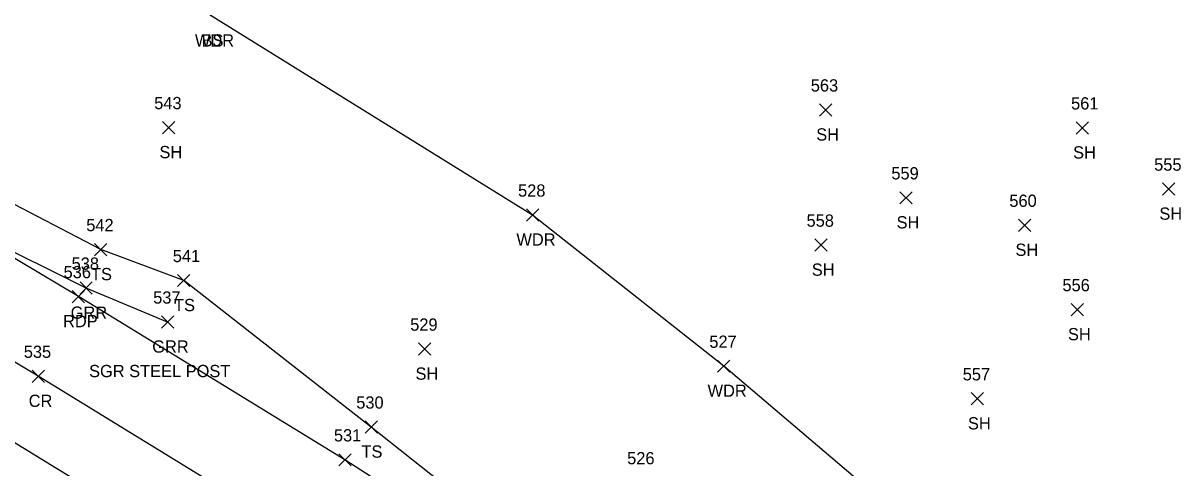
# Model space of a CAD drawing. Extents: x 1629176 to 1637209, y 606063 to 610167.
# Drawn here: x 1630613 to 1630801.8, y 606647 to 606719.6 of the extents above; entities that cross this region are included whole.
import ezdxf

# ---------------------------------------------------------------- set-up
doc = ezdxf.new("R2010")
doc.units = 0
for name, color, linetype in [('L_A', 7, 'Continuous'), ('L_I', 7, 'Continuous'), ('L_TIC', 7, 'Continuous'), ('LAWA', 7, 'Continuous'), ('LELB', 7, 'Continuous'), ('P_A', 7, 'Continuous'), ('P_I', 7, 'Continuous'), ('P_TIC', 7, 'Continuous'), ('PET', 7, 'Continuous'), ('PRC', 7, 'Continuous'), ('R_A', 7, 'Continuous'), ('R_C', 7, 'Continuous'), ('R_I', 7, 'Continuous'), ('R_TIC', 7, 'Continuous'), ('RGR', 7, 'Continuous')]:
    doc.layers.add(name, color=color, linetype=linetype)

msp = doc.modelspace()

# ---------------------------------------------------------------- linework, layer by layer
at = {"layer": 'L_TIC'}
for points in [[(1630742.83, 606704.44), (1630744.83, 606706.44)], [(1630744.83, 606704.44), (1630742.83, 606706.44)], [(1630635.7, 606701.56), (1630637.7, 606703.56)], [(1630637.7, 606701.56), (1630635.7, 606703.56)], [(1630784.72, 606701.51), (1630786.72, 606703.51)], [(1630786.72, 606701.51), (1630784.72, 606703.51)], [(1630798.78, 606691.52), (1630800.78, 606693.52)], [(1630800.78, 606691.52), (1630798.78, 606693.52)], [(1630755.93, 606690.1), (1630757.93, 606692.1)], [(1630757.93, 606690.1), (1630755.93, 606692.1)], [(1630695.05, 606687.29), (1630697.05, 606689.29)], [(1630697.05, 606687.29), (1630695.05, 606689.29)], [(1630775.3, 606685.62), (1630777.3, 606687.62)], [(1630777.3, 606685.62), (1630775.3, 606687.62)], [(1630742.1, 606682.38), (1630744.1, 606684.38)], [(1630744.1, 606682.38), (1630742.1, 606684.38)], [(1630624.62, 606681.65), (1630626.62, 606683.65)], [(1630626.62, 606681.65), (1630624.62, 606683.65)], [(1630638.16, 606676.6), (1630640.16, 606678.6)], [(1630640.16, 606676.6), (1630638.16, 606678.6)], [(1630783.87, 606671.85), (1630785.87, 606673.85)], [(1630785.87, 606671.85), (1630783.87, 606673.85)], [(1630677.46, 606665.41), (1630679.46, 606667.41)], [(1630679.46, 606665.41), (1630677.46, 606667.41)], [(1630726.23, 606662.62), (1630728.23, 606664.62)], [(1630728.23, 606662.62), (1630726.23, 606664.62)], [(1630767.56, 606657.3), (1630769.56, 606659.3)], [(1630769.56, 606657.3), (1630767.56, 606659.3)], [(1630668.73, 606652.69), (1630670.73, 606654.69)], [(1630670.73, 606652.69), (1630668.73, 606654.69)]]:
    msp.add_lwpolyline(points, dxfattribs=at)
at = {"layer": 'LAWA'}
msp.add_lwpolyline([(1630792.9, 606615.3), (1630764.71, 606631.77), (1630727.23, 606663.62), (1630696.05, 606688.29), (1630643.61, 606720.78), (1630609.4, 606762.16), (1630595.94, 606778.67), (1630581.31, 606798.55), (1630556.61, 606821.27), (1630561.53, 606852.75)], dxfattribs=at)
at = {"layer": 'LELB'}
msp.add_lwpolyline([(1630772.3, 606583.26), (1630744.36, 606600.82), (1630702.09, 606628.01), (1630669.73, 606653.69), (1630639.16, 606677.6), (1630625.62, 606682.65), (1630575.5, 606708.79), (1630543.73, 606726.11), (1630517.88, 606742.14), (1630478.23, 606762.96), (1630430.43, 606788.65), (1630392.8, 606806.98), (1630357.66, 606823.31), (1630317.9, 606842.29), (1630273.51, 606862.27), (1630239.69, 606876.29), (1630209.67, 606888.82), (1630166.54, 606905.65), (1630125.1, 606921.22), (1630084.2, 606935.53), (1630049.16, 606947.36)], dxfattribs=at)
at = {"layer": 'P_TIC'}
for points in [[(1630620.98, 606673.98), (1630622.98, 606675.98)], [(1630622.98, 606673.98), (1630620.98, 606675.98)], [(1630614.44, 606660.97), (1630616.44, 606662.97)], [(1630616.44, 606660.97), (1630614.44, 606662.97)], [(1630664.45, 606647.34), (1630666.45, 606649.34)], [(1630666.45, 606647.34), (1630664.45, 606649.34)]]:
    msp.add_lwpolyline(points, dxfattribs=at)
at = {"layer": 'PET'}
msp.add_lwpolyline([(1630769.62, 606580.83), (1630742.32, 606598.72), (1630700.55, 606625.63), (1630665.45, 606648.34), (1630621.98, 606674.98), (1630606.18, 606684.39), (1630572.37, 606704.1), (1630541.12, 606722.17), (1630498.96, 606745.43), (1630457.51, 606767.81), (1630420.78, 606786.67), (1630374.62, 606809.25), (1630335.12, 606827.65), (1630289.38, 606848.42), (1630250.13, 606865.31), (1630203.69, 606884.49), (1630159.86, 606901.83), (1630115.59, 606918.47), (1630070.26, 606934.37)], dxfattribs=at)
at = {"layer": 'PRC'}
for points in [[(1630762, 606568.31), (1630732.48, 606587.66), (1630693.14, 606613.4), (1630657.5, 606636.16), (1630615.44, 606661.97), (1630565.18, 606692.12), (1630533.4, 606710.56), (1630491.42, 606733.47), (1630450.45, 606755.19), (1630412.78, 606774.87), (1630369.5, 606796.13), (1630328.6, 606815.23), (1630283.03, 606835.75), (1630244.34, 606852.21), (1630197.18, 606871.73), (1630154.28, 606888.46), (1630110.18, 606905.77), (1630065.36, 606921.68)], [(1630755.45, 606559.52), (1630726, 606578.65), (1630686.27, 606604.3), (1630651.63, 606626.53), (1630610.5, 606651.79), (1630559.24, 606682.64), (1630527.45, 606700.94), (1630485.76, 606723.98), (1630445.96, 606745.41), (1630407.11, 606765.59), (1630364.16, 606786.66), (1630323.37, 606805.55), (1630278.9, 606825.47), (1630240.3, 606842.26), (1630192.63, 606861.5), (1630149.2, 606878.91), (1630105.99, 606894.95), (1630061.18, 606910.94)]]:
    msp.add_lwpolyline(points, dxfattribs=at)
at = {"layer": 'R_TIC'}
for points in [[(1630622.24, 606675.36), (1630624.24, 606677.36)], [(1630624.24, 606675.36), (1630622.24, 606677.36)], [(1630635.53, 606669.83), (1630637.53, 606671.83)], [(1630637.53, 606669.83), (1630635.53, 606671.83)]]:
    msp.add_lwpolyline(points, dxfattribs=at)
at = {"layer": 'RGR'}
msp.add_lwpolyline([(1630636.53, 606670.83), (1630623.24, 606676.36), (1630606.52, 606684.67), (1630573.19, 606704.3), (1630541.55, 606722.4), (1630499.19, 606745.82), (1630457.55, 606768.16), (1630421.01, 606787.01), (1630374.76, 606809.6), (1630335.39, 606828.12), (1630289.48, 606848.85), (1630250.07, 606865.82), (1630203.7, 606885.03), (1630160.01, 606902.28), (1630115.67, 606918.76), (1630070.66, 606934.74)], dxfattribs=at)

# ---------------------------------------------------------------- texts
at = {"layer": 'L_A'}
for s, p in [('WDR', (1630640.98, 606715.78)), ('BS', (1630642.06, 606715.78)), ('SH', (1630742.31, 606700.44)), ('SH', (1630635.19, 606697.56)), ('SH', (1630784.2, 606697.51)), ('SH', (1630755.41, 606686.1)), ('SH', (1630798.27, 606687.52)), ('WDR', (1630693.41, 606683.29)), ('SH', (1630774.79, 606681.62)), ('SH', (1630741.58, 606678.38)), ('TS', (1630624.03, 606677.65)), ('TS', (1630637.57, 606672.6)), ('SH', (1630783.36, 606667.85)), ('SH', (1630676.95, 606661.41)), ('WDR', (1630724.59, 606658.62)), ('SH', (1630767.05, 606653.3)), ('TS', (1630668.14, 606648.69))]:
    msp.add_text(s, height=2, dxfattribs=at).set_placement(p)
at = {"layer": 'L_I'}
for s, p in [('563', (1630741.42, 606708.44)), ('543', (1630634.34, 606705.56)), ('561', (1630783.87, 606705.51)), ('555', (1630797.42, 606695.52)), ('559', (1630754.56, 606694.1)), ('528', (1630693.68, 606691.29)), ('560', (1630773.8, 606689.62)), ('558', (1630740.73, 606686.38)), ('542', (1630623.26, 606685.65)), ('541', (1630637.37, 606680.6)), ('556', (1630782.46, 606675.85)), ('529', (1630676.09, 606669.41)), ('527', (1630724.87, 606666.62)), ('557', (1630766.2, 606661.3)), ('530', (1630667.29, 606656.69)), ('526', (1630711.47, 606647.61))]:
    msp.add_text(s, height=2, dxfattribs=at).set_placement(p)
at = {"layer": 'P_A'}
for s, p in [('RDP', (1630619.47, 606669.98)), ('CR', (1630613.87, 606656.97))]:
    msp.add_text(s, height=2, dxfattribs=at).set_placement(p)
at = {"layer": 'P_I'}
for s, p in [('536', (1630619.56, 606677.98)), ('535', (1630613.07, 606664.97)), ('531', (1630663.65, 606651.34))]:
    msp.add_text(s, height=2, dxfattribs=at).set_placement(p)
at = {"layer": 'R_A'}
for p in [(1630620.72, 606671.36), (1630634.02, 606665.83)]:
    msp.add_text('GRR', height=2, dxfattribs=at).set_placement(p)
at = {"layer": 'R_C'}
msp.add_text('SGR STEEL POST', height=2, dxfattribs=at).set_placement((1630623.72, 606661.83))
at = {"layer": 'R_I'}
for s, p in [('538', (1630620.87, 606679.36)), ('537', (1630634.17, 606673.83))]:
    msp.add_text(s, height=2, dxfattribs=at).set_placement(p)

doc.saveas('drawing.dxf')
